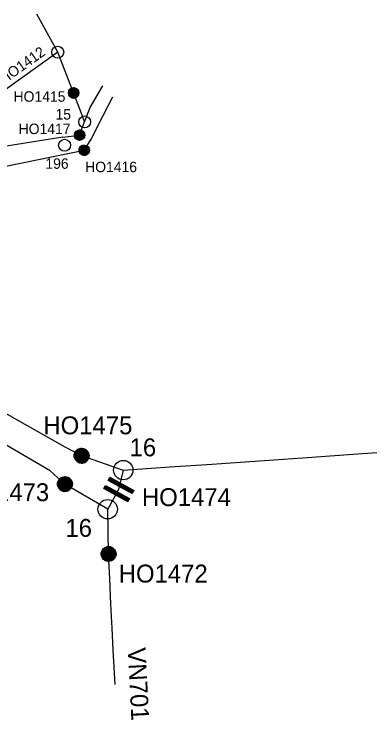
# Model space of a CAD drawing. Extents: x -546092 to -542700, y -1196659 to -1193917.
# Drawn here: x -543918 to -542700, y -1196659 to -1194292 of the extents above; entities that cross this region are included whole.
import ezdxf

# ---------------------------------------------------------------- set-up
doc = ezdxf.new("R2010")
doc.units = 0
for name, color, linetype in [('Default', 7, 'Continuous'), ('Vrstva 1', 7, 'Continuous'), ('Vrstva 2', 7, 'Continuous'), ('Vrstva 5', 7, 'Continuous')]:
    doc.layers.add(name, color=color, linetype=linetype)

# ---------------------------------------------------------------- blocks, each defined once
blk = doc.blocks.new('PS100')
at = {"layer": 'Default'}
for p, q in [((-17.5, -0.7), (0.7, 17.5)), ((-17.5, 0.7), (-0.7, 17.5)), ((-17.4, -2), (2, 17.4)), ((-17.3, 2.2), (-2.2, 17.3)), ((-17.2, -3.3), (3.3, 17.2)), ((-17, 4), (-4, 17)), ((-16.9, -4.4), (4.4, 16.9)), ((-16.6, -5.5), (5.5, 16.6)), ((-16.4, 6), (-6, 16.4)), ((-16.2, -6.5), (6.5, 16.2)), ((-15.8, -7.5), (7.5, 15.8)), ((-15.3, -8.4), (8.4, 15.3)), ((-15.2, 8.6), (-8.6, 15.2)), ((-14.8, -9.3), (9.3, 14.8)), ((-14.2, -10.2), (10.2, 14.2)), ((-13.6, -11), (11, 13.6)), ((-13, -11.7), (11.7, 13)), ((-12.3, -12.5), (12.5, 12.3)), ((-11.5, -13.2), (13.2, 11.5)), ((-10.8, -13.8), (13.8, 10.8)), ((-9.9, -14.4), (14.4, 9.9)), ((-9.1, -14.9), (14.9, 9.1)), ((-8.2, -15.5), (15.5, 8.2)), ((-7.2, -15.9), (15.9, 7.2)), ((-6.2, -16.3), (16.3, 6.2)), ((-5.2, -16.7), (16.7, 5.2)), ((-4.1, -17), (17, 4.1)), ((-2.9, -17.2), (17.2, 2.9)), ((-1.6, -17.4), (17.4, 1.6)), ((-0.3, -17.5), (17.5, 0.3)), ((1.1, -17.4), (17.4, -1.1)), ((2.7, -17.3), (17.3, -2.7)), ((4.5, -16.9), (16.9, -4.5)), ((6.7, -16.2), (16.2, -6.7)), ((9.7, -14.5), (14.5, -9.7))]:
    blk.add_line(p, q, dxfattribs=at)
blk.add_circle((0, 0), 17.5, dxfattribs=at)
blk = doc.blocks.new('PS140')
at = {"layer": 'Default'}
for p, q in [((-17.5, 0), (0, 17.5)), ((-17.4, -1.4), (1.4, 17.4)), ((-17.4, 1.5), (-1.5, 17.4)), ((-17.3, -2.6), (2.6, 17.3)), ((-17.2, 3.1), (-3.1, 17.2)), ((-17.1, -3.8), (3.8, 17.1)), ((-16.8, -4.9), (4.9, 16.8)), ((-16.8, 5), (-5, 16.8)), ((-16.4, -6), (6, 16.4)), ((-16, -7), (7, 16)), ((-15.9, 7.2), (-7.2, 15.9)), ((-15.6, -8), (8, 15.6)), ((-15.1, -8.9), (8.9, 15.1)), ((-14.5, -9.8), (9.8, 14.5)), ((-13.9, -10.6), (10.6, 13.9)), ((-13.8, 10.8), (-10.8, 13.8)), ((-13.3, -11.4), (11.4, 13.3)), ((-12.6, -12.1), (12.1, 12.6)), ((-11.9, -12.8), (12.8, 11.9)), ((-11.2, -13.5), (13.5, 11.2)), ((-10.4, -14.1), (14.1, 10.4)), ((-9.5, -14.7), (14.7, 9.5)), ((-8.6, -15.2), (15.2, 8.6)), ((-7.7, -15.7), (15.7, 7.7)), ((-6.7, -16.1), (16.1, 6.7)), ((-5.7, -16.5), (16.5, 5.7)), ((-4.6, -16.9), (16.9, 4.6)), ((-3.5, -17.1), (17.1, 3.5)), ((-2.3, -17.3), (17.3, 2.3)), ((-1, -17.5), (17.5, 1)), ((0.4, -17.5), (17.5, -0.4)), ((1.9, -17.4), (17.4, -1.9)), ((3.6, -17.1), (17.1, -3.6)), ((5.5, -16.6), (16.6, -5.5)), ((8, -15.6), (15.6, -8))]:
    blk.add_line(p, q, dxfattribs=at)
blk.add_circle((0, 0), 17.5, dxfattribs=at)
blk = doc.blocks.new('PS300')
at = {"layer": 'Default'}
for p, q in [((-25, 0.1), (-0.1, 25)), ((-24.9, -1.2), (1.2, 24.9)), ((-24.9, 1.6), (-1.6, 24.9)), ((-24.8, -2.6), (2.6, 24.8)), ((-24.8, 3.2), (-3.2, 24.8)), ((-24.7, -3.8), (3.8, 24.7)), ((-24.5, -5), (5, 24.5)), ((-24.5, 4.9), (-4.9, 24.5)), ((-24.2, -6.2), (6.2, 24.2)), ((-24.1, 6.7), (-6.7, 24.1)), ((-23.9, -7.3), (7.3, 23.9)), ((-23.6, -8.3), (8.3, 23.6)), ((-23.4, 8.8), (-8.8, 23.4)), ((-23.2, -9.4), (9.4, 23.2)), ((-22.7, -10.3), (10.3, 22.7)), ((-22.3, -11.3), (11.3, 22.3)), ((-22.3, 11.3), (-11.3, 22.3)), ((-21.8, -12.2), (12.2, 21.8)), ((-21.3, -13.1), (13.1, 21.3)), ((-20.7, -14), (14, 20.7)), ((-20.1, -14.8), (14.8, 20.1)), ((-19.9, 15.2), (-15.2, 19.9)), ((-19.5, -15.6), (15.6, 19.5)), ((-18.9, -16.4), (16.4, 18.9)), ((-18.2, -17.1), (17.1, 18.2)), ((-17.5, -17.8), (17.8, 17.5)), ((-16.8, -18.5), (18.5, 16.8)), ((-16, -19.2), (19.2, 16)), ((-15.2, -19.8), (19.8, 15.2)), ((-14.4, -20.4), (20.4, 14.4)), ((-13.6, -21), (21, 13.6)), ((-12.7, -21.5), (21.5, 12.7)), ((-11.8, -22), (22, 11.8)), ((-10.8, -22.5), (22.5, 10.8)), ((-9.9, -22.9), (22.9, 9.9)), ((-8.9, -23.4), (23.4, 8.9)), ((-7.8, -23.7), (23.7, 7.8)), ((-6.7, -24.1), (24.1, 6.7)), ((-5.6, -24.3), (24.3, 5.6)), ((-4.4, -24.6), (24.6, 4.4)), ((-3.2, -24.8), (24.8, 3.2)), ((-1.9, -24.9), (24.9, 1.9)), ((-0.6, -25), (25, 0.6)), ((0.8, -25), (25, -0.8)), ((2.3, -24.9), (24.9, -2.3)), ((4, -24.7), (24.7, -4)), ((5.7, -24.3), (24.3, -5.7)), ((7.7, -23.8), (23.8, -7.7)), ((10, -22.9), (22.9, -10)), ((12.9, -21.4), (21.4, -12.9))]:
    blk.add_line(p, q, dxfattribs=at)
blk.add_circle((0, 0), 25, dxfattribs=at)
blk = doc.blocks.new('PS440')
at = {"layer": 'Default'}
for p, q in [((-25, 0.1), (-0.1, 25)), ((-24.9, -1.2), (1.2, 24.9)), ((-24.9, 1.6), (-1.6, 24.9)), ((-24.8, -2.6), (2.6, 24.8)), ((-24.8, 3.2), (-3.2, 24.8)), ((-24.7, -3.8), (3.8, 24.7)), ((-24.5, -5), (5, 24.5)), ((-24.5, 4.9), (-4.9, 24.5)), ((-24.2, -6.2), (6.2, 24.2)), ((-24.1, 6.7), (-6.7, 24.1)), ((-23.9, -7.3), (7.3, 23.9)), ((-23.6, -8.3), (8.3, 23.6)), ((-23.4, 8.8), (-8.8, 23.4)), ((-23.2, -9.4), (9.4, 23.2)), ((-22.7, -10.3), (10.3, 22.7)), ((-22.3, -11.3), (11.3, 22.3)), ((-22.3, 11.3), (-11.3, 22.3)), ((-21.8, -12.2), (12.2, 21.8)), ((-21.3, -13.1), (13.1, 21.3)), ((-20.7, -14), (14, 20.7)), ((-20.1, -14.8), (14.8, 20.1)), ((-19.9, 15.2), (-15.2, 19.9)), ((-19.5, -15.6), (15.6, 19.5)), ((-18.9, -16.4), (16.4, 18.9)), ((-18.2, -17.1), (17.1, 18.2)), ((-17.5, -17.8), (17.8, 17.5)), ((-16.8, -18.5), (18.5, 16.8)), ((-16, -19.2), (19.2, 16)), ((-15.2, -19.8), (19.8, 15.2)), ((-14.4, -20.4), (20.4, 14.4)), ((-13.6, -21), (21, 13.6)), ((-12.7, -21.5), (21.5, 12.7)), ((-11.8, -22), (22, 11.8)), ((-10.8, -22.5), (22.5, 10.8)), ((-9.9, -22.9), (22.9, 9.9)), ((-8.9, -23.4), (23.4, 8.9)), ((-7.8, -23.7), (23.7, 7.8)), ((-6.7, -24.1), (24.1, 6.7)), ((-5.6, -24.3), (24.3, 5.6)), ((-4.4, -24.6), (24.6, 4.4)), ((-3.2, -24.8), (24.8, 3.2)), ((-1.9, -24.9), (24.9, 1.9)), ((-0.6, -25), (25, 0.6)), ((0.8, -25), (25, -0.8)), ((2.3, -24.9), (24.9, -2.3)), ((4, -24.7), (24.7, -4)), ((5.7, -24.3), (24.3, -5.7)), ((7.7, -23.8), (23.8, -7.7)), ((10, -22.9), (22.9, -10)), ((12.9, -21.4), (21.4, -12.9))]:
    blk.add_line(p, q, dxfattribs=at)
blk.add_circle((0, 0), 25, dxfattribs=at)
blk = doc.blocks.new('PS820')
at = {"layer": 'Vrstva 2'}
blk.add_circle((0, 0), 32.5, dxfattribs=at)
blk = doc.blocks.new('PS450')
at = {"layer": 'Default'}
for p, q in [((-22.1, 35.1), (-10.4, 46.8)), ((-22.1, 36.5), (-11.8, 46.8)), ((-22.1, 38), (-13.3, 46.8)), ((-22.1, 39.4), (-14.7, 46.8)), ((-22.1, 40.8), (-16.1, 46.8)), ((-22.1, 42.2), (-17.5, 46.8)), ((-22.1, 43.6), (-18.9, 46.8)), ((-22.1, 45), (-20.3, 46.8)), ((-22.1, 46.4), (-21.7, 46.8)), ((-22.1, 33.7), (-9.9, 45.9)), ((-22.1, 32.3), (-9.9, 44.5)), ((-22.1, 30.9), (-9.9, 43.1)), ((-22.1, 29.5), (-9.9, 41.7)), ((-22.1, 28.1), (-9.9, 40.3)), ((-22.1, 26.6), (-9.9, 38.9)), ((-22.1, 25.2), (-9.9, 37.5)), ((-22.1, 23.8), (-9.9, 36)), ((-22.1, 22.4), (-9.9, 34.6)), ((-22.1, 21), (-9.9, 33.2)), ((-22.1, 19.6), (-9.9, 31.8)), ((-22.1, 18.2), (-9.9, 30.4)), ((-22.1, 16.7), (-9.9, 29)), ((-22.1, 15.3), (-9.9, 27.6)), ((-22.1, 13.9), (-9.9, 26.1)), ((-22.1, 12.5), (-9.9, 24.7)), ((8.9, 35.2), (20.5, 46.8)), ((8.9, 36.7), (19.1, 46.8)), ((8.9, 38.1), (17.6, 46.8)), ((8.9, 39.5), (16.2, 46.8)), ((8.9, 40.9), (14.8, 46.8)), ((8.9, 42.3), (13.4, 46.8)), ((8.9, 43.7), (12, 46.8)), ((8.9, 45.1), (10.6, 46.8)), ((8.9, 46.6), (9.2, 46.8)), ((8.9, 33.8), (21.1, 46.1)), ((8.9, 32.4), (21.1, 44.6)), ((8.9, 31), (21.1, 43.2)), ((8.9, 29.6), (21.1, 41.8)), ((8.9, 28.2), (21.1, 40.4)), ((8.9, 26.8), (21.1, 39)), ((8.9, 25.3), (21.1, 37.6)), ((8.9, 23.9), (21.1, 36.2)), ((8.9, 22.5), (21.1, 34.7)), ((8.9, 21.1), (21.1, 33.3)), ((8.9, 19.7), (21.1, 31.9)), ((8.9, 18.3), (21.1, 30.5)), ((8.9, 16.9), (21.1, 29.1)), ((8.9, 15.5), (21.1, 27.7)), ((8.9, 14), (21.1, 26.3)), ((8.9, 12.6), (21.1, 24.9)), ((-22.1, 11.1), (-9.9, 23.3)), ((-22.1, 9.7), (-9.9, 21.9)), ((-22.1, 8.3), (-9.9, 20.5)), ((-22.1, 6.8), (-9.9, 19.1)), ((-22.1, 5.4), (-9.9, 17.7)), ((-22.1, 4), (-9.9, 16.2)), ((-22.1, 2.6), (-9.9, 14.8)), ((-22.1, 1.2), (-9.9, 13.4)), ((-22.1, -0.2), (-9.9, 12)), ((-22.1, -1.6), (-9.9, 10.6)), ((-22.1, -3.1), (-9.9, 9.2)), ((-22.1, -4.5), (-9.9, 7.8)), ((-22.1, -5.9), (-9.9, 6.3)), ((-22.1, -7.3), (-9.9, 4.9)), ((-22.1, -8.7), (-9.9, 3.5)), ((-22.1, -10.1), (-9.9, 2.1)), ((-22.1, -11.5), (-9.9, 0.7)), ((8.9, 11.2), (21.1, 23.4)), ((8.9, 9.8), (21.1, 22)), ((8.9, 8.4), (21.1, 20.6)), ((8.9, 7), (21.1, 19.2)), ((8.9, 5.6), (21.1, 17.8)), ((8.9, 4.1), (21.1, 16.4)), ((8.9, 2.7), (21.1, 15)), ((8.9, 1.3), (21.1, 13.5)), ((8.9, -0.1), (21.1, 12.1)), ((8.9, -1.5), (21.1, 10.7)), ((8.9, -2.9), (21.1, 9.3)), ((8.9, -4.3), (21.1, 7.9)), ((8.9, -5.8), (21.1, 6.5)), ((8.9, -7.2), (21.1, 5.1)), ((8.9, -8.6), (21.1, 3.6)), ((8.9, -10), (21.1, 2.2)), ((8.9, -11.4), (21.1, 0.8)), ((-22.1, -13), (-9.9, -0.7)), ((-22.1, -14.4), (-9.9, -2.1)), ((-22.1, -15.8), (-9.9, -3.6)), ((-22.1, -17.2), (-9.9, -5)), ((-22.1, -18.6), (-9.9, -6.4)), ((-22.1, -20), (-9.9, -7.8)), ((-22.1, -21.4), (-9.9, -9.2)), ((-22.1, -22.9), (-9.9, -10.6)), ((-22.1, -24.3), (-9.9, -12)), ((-22.1, -25.7), (-9.9, -13.5)), ((-22.1, -27.1), (-9.9, -14.9)), ((-22.1, -28.5), (-9.9, -16.3)), ((-22.1, -29.9), (-9.9, -17.7)), ((-22.1, -31.3), (-9.9, -19.1)), ((-22.1, -32.8), (-9.9, -20.5)), ((-22.1, -34.2), (-9.9, -21.9)), ((-22.1, -35.6), (-9.9, -23.4)), ((8.9, -12.8), (21.1, -0.6)), ((8.9, -14.2), (21.1, -2)), ((8.9, -15.7), (21.1, -3.4)), ((8.9, -17.1), (21.1, -4.8)), ((8.9, -18.5), (21.1, -6.3)), ((8.9, -19.9), (21.1, -7.7)), ((8.9, -21.3), (21.1, -9.1)), ((8.9, -22.7), (21.1, -10.5)), ((8.9, -24.1), (21.1, -11.9)), ((8.9, -25.6), (21.1, -13.3)), ((8.9, -27), (21.1, -14.7)), ((8.9, -28.4), (21.1, -16.2)), ((8.9, -29.8), (21.1, -17.6)), ((8.9, -31.2), (21.1, -19)), ((8.9, -32.6), (21.1, -20.4)), ((8.9, -34), (21.1, -21.8)), ((8.9, -35.5), (21.1, -23.2)), ((-22.1, -37), (-9.9, -24.8)), ((-22.1, -38.4), (-9.9, -26.2)), ((-22.1, -39.8), (-9.9, -27.6)), ((-22.1, -41.2), (-9.9, -29)), ((-22.1, -42.7), (-9.9, -30.4)), ((-22.1, -44.1), (-9.9, -31.8)), ((-21.5, -44.9), (-9.9, -33.3)), ((-20.1, -44.9), (-9.9, -34.7)), ((-18.7, -44.9), (-9.9, -36.1)), ((-17.3, -44.9), (-9.9, -37.5)), ((-15.8, -44.9), (-9.9, -38.9)), ((-14.4, -44.9), (-9.9, -40.3)), ((-13, -44.9), (-9.9, -41.7)), ((-11.6, -44.9), (-9.9, -43.2)), ((-10.2, -44.9), (-9.9, -44.6)), ((8.9, -36.9), (21.1, -24.6)), ((8.9, -38.3), (21.1, -26.1)), ((8.9, -39.7), (21.1, -27.5)), ((8.9, -41.1), (21.1, -28.9)), ((8.9, -42.5), (21.1, -30.3)), ((8.9, -43.9), (21.1, -31.7)), ((9.4, -44.9), (21.1, -33.1)), ((10.8, -44.9), (21.1, -34.5)), ((12.2, -44.9), (21.1, -36)), ((13.6, -44.9), (21.1, -37.4)), ((15, -44.9), (21.1, -38.8)), ((16.5, -44.9), (21.1, -40.2)), ((17.9, -44.9), (21.1, -41.6)), ((19.3, -44.9), (21.1, -43)), ((20.7, -44.9), (21.1, -44.4))]:
    blk.add_line(p, q, dxfattribs=at)
for points in [[(-9.9, 46.8), (-9.9, -44.9), (-22.1, -44.9), (-22.1, 46.8)], [(21.1, 46.8), (21.1, -44.9), (8.9, -44.9), (8.9, 46.8)]]:
    blk.add_lwpolyline(points, close=True, dxfattribs=at)
blk = doc.blocks.new('PS800')
at = {"layer": 'Vrstva 2'}
blk.add_circle((0, 0), 20, dxfattribs=at)

msp = doc.modelspace()

# ---------------------------------------------------------------- linework, layer by layer
at = {"layer": 'Vrstva 1'}
for points in [[(-543771.7, -1194419.4), (-543842.4, -1194291.7)], [(-543771.7, -1194419.4), (-543957.5, -1194552.9)], [(-543718.4, -1194555.8), (-543771.7, -1194419.4)], [(-543681.5, -1194653.4), (-543663.1, -1194605.4), (-543620.7, -1194532.1)], [(-543681.5, -1194653.4), (-543693.4, -1194621.9), (-543718.4, -1194555.8)], [(-543661.2, -1194713.7), (-543618.9, -1194631.6), (-543586.6, -1194569.1)], [(-543698.5, -1194697.8), (-543698.5, -1194697.8), (-543681.5, -1194653.4)], [(-543754.5, -1194704), (-543698.5, -1194697.8)], [(-543754.5, -1194704), (-544879, -1194883.4)], [(-543682.9, -1194748.4), (-543661.2, -1194713.7)], [(-544664.8, -1194948.5), (-543682.9, -1194748.4)], [(-544877.9, -1195104.9), (-543747.9, -1195742.8)], [(-543797.6, -1195824.2), (-544918, -1195169.5)], [(-543747.9, -1195742.8), (-543691.6, -1195772.8)], [(-543551.6, -1195821.2), (-543473.3, -1195815.8), (-543379, -1195809.5), (-543270.4, -1195802.1), (-543142.2, -1195793.3), (-543029, -1195785.3), (-542902.9, -1195776.7), (-542795.1, -1195769.2), (-542699.8, -1195762.6)], [(-543691.6, -1195772.8), (-543551.6, -1195821.2)], [(-543747.6, -1195868), (-543797.6, -1195824.2)], [(-543551.6, -1195821.2), (-543551.6, -1195821.2), (-543567.8, -1195886.2), (-543567.8, -1195886.2)], [(-543604.1, -1195952.5), (-543747.6, -1195868)], [(-543567.8, -1195886.2), (-543567.8, -1195886.2), (-543604.1, -1195952.5), (-543604.1, -1195952.5)], [(-543601.1, -1196102.5), (-543604.1, -1195952.5)], [(-543579.2, -1196540), (-543580.2, -1196521.5), (-543585.2, -1196424.3), (-543588.6, -1196351.2), (-543593.3, -1196270.8), (-543597.2, -1196186.5), (-543601.1, -1196102.5)]]:
    msp.add_lwpolyline(points, dxfattribs=at)

# ---------------------------------------------------------------- block references
at = {"layer": 'Vrstva 2'}
for name, p, rotation in [('PS100', (-543718.4, -1194555.8), -71.91549724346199), ('PS140', (-543698.5, -1194697.8), 69.07686666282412), ('PS140', (-543682.9, -1194748.4), 6.8008972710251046), ('PS440', (-543691.6, -1195772.8), -5.391458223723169), ('PS440', (-543747.6, -1195868), -27.67118053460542), ('PS450', (-543567.8, -1195886.2), -118.67840981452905), ('PS300', (-543601.1, -1196102.5), -87.29051664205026)]:
    msp.add_blockref(name, p, dxfattribs=dict(at, rotation=rotation))
at = {"layer": 'Vrstva 5'}
for name, p, rotation in [('PS800', (-543771.7, -1194419.4), -71.91549717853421), ('PS800', (-543681.5, -1194653.4), 69.0549666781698), ('PS820', (-543551.6, -1195821.2), 3.934969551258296), ('PS820', (-543604.1, -1195952.5), -30.046622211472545)]:
    msp.add_blockref(name, p, dxfattribs=dict(at, rotation=rotation))
msp.add_blockref('PS800', (-543748.8, -1194731.6), dxfattribs=at)

# ---------------------------------------------------------------- texts
at = {"layer": 'Vrstva 1'}
msp.add_text('VN701', height=60, rotation=272.967, dxfattribs=at).set_placement((-543537, -1196418))
at = {"layer": 'Vrstva 2'}
msp.add_text('HO1412', height=35, rotation=35.383, dxfattribs=at).set_placement((-543952.5, -1194527.5))
for s, height, p in [('HO1415', 35, (-543920.2, -1194585.6)), ('HO1417', 35, (-543903.2, -1194694.1)), ('HO1416', 35, (-543679.8, -1194821.8)), ('HO1475', 60, (-543820, -1195701.1)), ('HO1473', 60, (-544099.4, -1195925.4)), ('HO1474', 60, (-543489.1, -1195942)), ('HO1472', 60, (-543566.9, -1196198.3))]:
    msp.add_text(s, height=height, dxfattribs=at).set_placement(p)
at = {"layer": 'Vrstva 5'}
for s, height, p in [('15', 35, (-543779.3, -1194645.3)), ('196', 35, (-543813.3, -1194810.5)), ('16', 60, (-543530.5, -1195774.9)), ('16', 60, (-543746.1, -1196045.1))]:
    msp.add_text(s, height=height, dxfattribs=at).set_placement(p)

doc.saveas('drawing.dxf')
